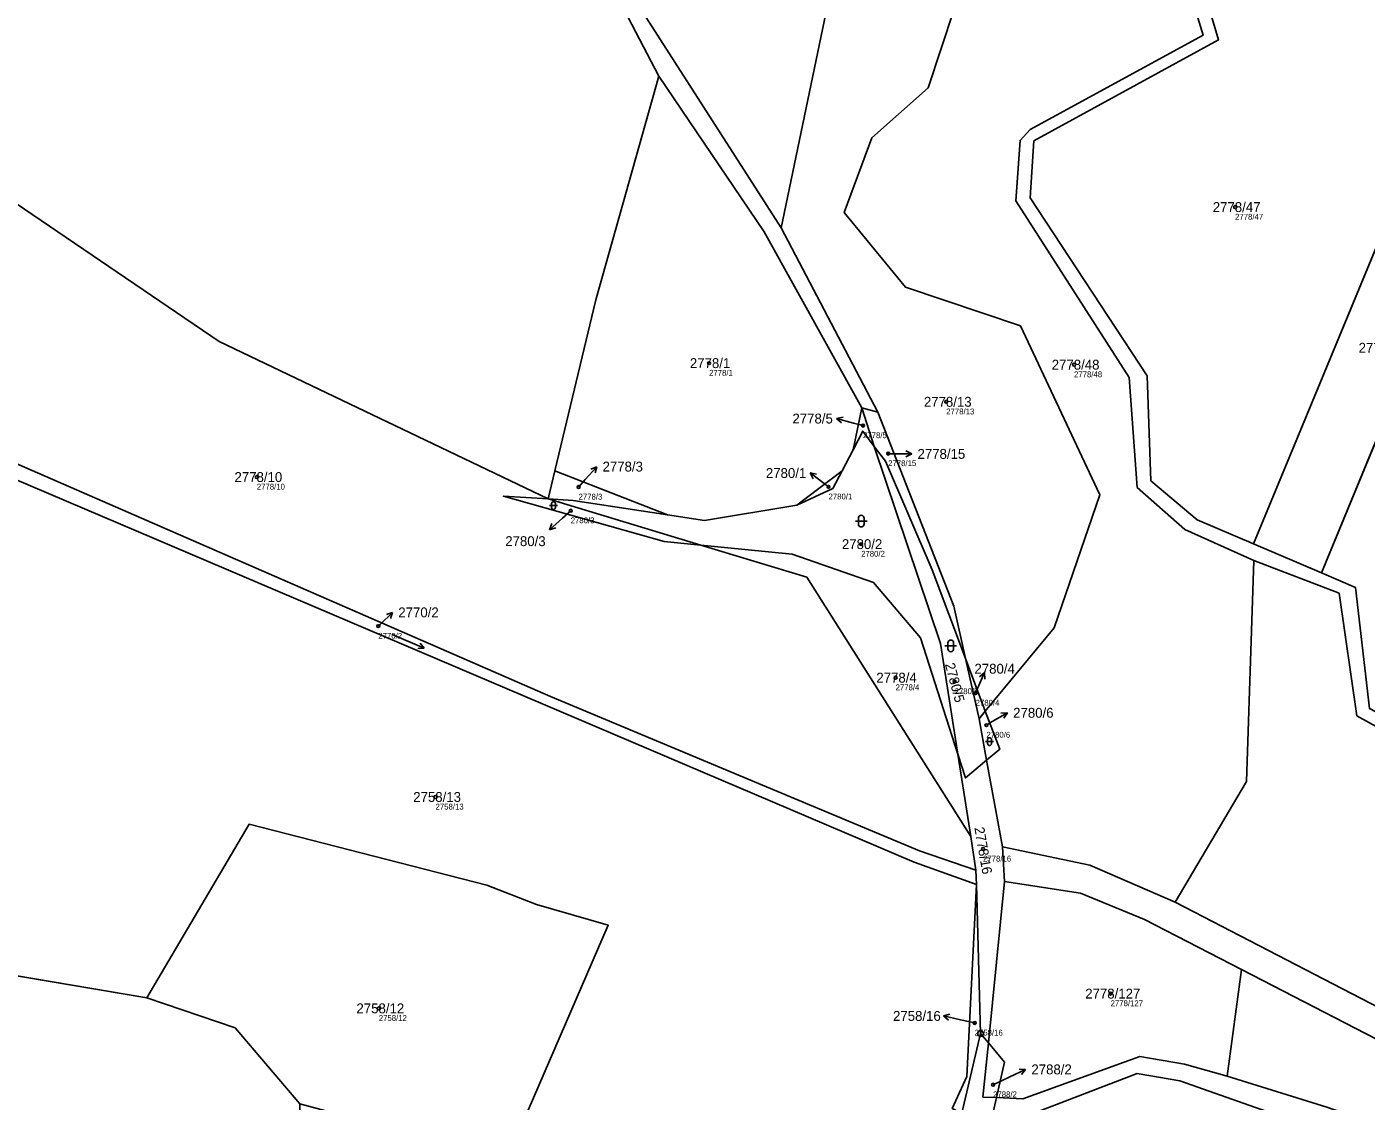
# Model space of a CAD drawing. Extents: x -739214 to -733252, y -1147612 to -1142842.
# Drawn here: x -738174 to -737943.5, y -1144060.6 to -1143875.8 of the extents above; entities that cross this region are included whole.
import ezdxf

# ---------------------------------------------------------------- set-up
doc = ezdxf.new("R2010")
doc.units = 0
for name, color, linetype in [('Definiční body', 7, 'Continuous'), ('Hranice parcel', 7, 'Continuous'), ('Parcelní čísla', 7, 'Continuous'), ('Polygon parcely', 7, 'Continuous'), ('Pop  PČ popisy', 7, 'Continuous'), ('Značky bodu BP', 7, 'Continuous'), ('Značky kultur', 7, 'Continuous')]:
    doc.layers.add(name, color=color, linetype=linetype)

msp = doc.modelspace()

# ---------------------------------------------------------------- linework, layer by layer
at = {"layer": 'Definiční body'}
for centre in [(-737966.1, -1143906.79), (-738056.61, -1143933.63), (-737993.81, -1143933.89), (-738015.81, -1143940.28), (-738030.12, -1143944.37), (-738025.8, -1143949.18), (-738134.44, -1143953.22), (-738079.07, -1143954.94), (-738036.06, -1143954.91), (-738080.42, -1143959.01), (-738030.45, -1143964.76), (-738113.53, -1143978.87), (-738024.52, -1143987.73), (-738014.36, -1143988.4), (-738010.74, -1143990.38), (-738008.89, -1143995.89), (-738103.68, -1144008.25), (-738009.47, -1144017.19), (-737987.52, -1144042.07), (-738113.45, -1144044.61), (-738010.91, -1144047.12), (-738007.74, -1144057.74)]:
    msp.add_circle(centre, 0.25, dxfattribs=at)
at = {"layer": 'Hranice parcel'}
for p, q in [((-738067.97, -1143873.37), (-738044.22, -1143910.38)), ((-737962.92, -1143964.73), (-737928.65, -1143881.88)), ((-737951.23, -1143969.71), (-737919.32, -1143892.38)), ((-738044.22, -1143910.38), (-738027.56, -1143942.04)), ((-738031.84, -1143948.55), (-738030.32, -1143941.32)), ((-738030.32, -1143941.32), (-738027.56, -1143942.04)), ((-738028.18, -1143947.96), (-738030.32, -1143941.32)), ((-738033.69, -1143952.13), (-738031.84, -1143948.55)), ((-738083.17, -1143952.17), (-738084.33, -1143956.99)), ((-738083.17, -1143952.17), (-738063.76, -1143959.71)), ((-738041.51, -1143958.03), (-738033.69, -1143952.13)), ((-738084.33, -1143956.99), (-738058.03, -1143964.92)), ((-737951.23, -1143969.71), (-737962.92, -1143964.73)), ((-738012.49, -1143984.43), (-738009.08, -1143993.47)), ((-738012.49, -1143984.43), (-738010.16, -1143994.78)), ((-738010.16, -1143994.78), (-738009.08, -1143993.47)), ((-738008.85, -1144001.92), (-738010.16, -1143994.78)), ((-738011.6, -1144015.06), (-738013.82, -1144000.89)), ((-738006.12, -1144016.81), (-738008.85, -1144001.92)), ((-738010.7, -1144020.82), (-738011.6, -1144015.06)), ((-738005.79, -1144022.76), (-738006.12, -1144016.81)), ((-738010.6, -1144023.28), (-738010.7, -1144020.82)), ((-738009.89, -1144048.95), (-738010.6, -1144023.28)), ((-738008.56, -1144050.53), (-738005.79, -1144022.76)), ((-738182.49, -1144037.88), (-738153.39, -1144042.78)), ((-737964.98, -1144037.92), (-737967.49, -1144056.26)), ((-738013.1, -1144062.62), (-738009.89, -1144048.95)), ((-738009.89, -1144048.95), (-738008.56, -1144050.53)), ((-738007.14, -1144059.96), (-738007.93, -1144063.48))]:
    msp.add_line(p, q, dxfattribs=at)
for points in [[(-738065.26, -1143884.27), (-738091.73, -1143833.66), (-738103.08, -1143819.81), (-738132.34, -1143806.02), (-738171.18, -1143796.23)], [(-738180.98, -1143797.5), (-738199.77, -1143862.82), (-738207.28, -1143860.51), (-738207.77, -1143875.03), (-738179.98, -1143892.1), (-738180.4, -1143903.13), (-738140.92, -1143929.92), (-738084.33, -1143956.99)], [(-738044.22, -1143910.38), (-738036.53, -1143873.49), (-738031.79, -1143856.2), (-738028.28, -1143846.12)], [(-738009.08, -1143993.47), (-737997.26, -1143979.13), (-737989.38, -1143956.26), (-738003.04, -1143927.22), (-738022.83, -1143920.54), (-738033.34, -1143907.71), (-738028.6, -1143894.86), (-738018.91, -1143886.27), (-738014.46, -1143872.73), (-738021.06, -1143860.02)], [(-737975.48, -1143864.47), (-737971.61, -1143877.23), (-738001.39, -1143893.44), (-738003.11, -1143895.33), (-738003.85, -1143905.7), (-737984.35, -1143936.12), (-737982.97, -1143955.01), (-737974.74, -1143962.25), (-737962.9, -1143967.6)], [(-737962.92, -1143964.73), (-737972.6, -1143960.6), (-737980.58, -1143953.86), (-737981.23, -1143935.79), (-738001.39, -1143905.17), (-738000.73, -1143895.41), (-737968.96, -1143878.05), (-737972.8, -1143864.99)], [(-738065.26, -1143884.27), (-738076.08, -1143922.72), (-738083.17, -1143952.17)], [(-738030.32, -1143941.32), (-738047.12, -1143911.02), (-738065.26, -1143884.27)], [(-738010.7, -1144020.82), (-738020.43, -1144017.52), (-738083.92, -1143990.96), (-738199.57, -1143940.6)], [(-738027.56, -1143942.04), (-738014.52, -1143975.43), (-738012.49, -1143984.43)], [(-738031.84, -1143948.55), (-738030.17, -1143945.33), (-738028.18, -1143947.96)], [(-738010.6, -1144023.28), (-738021.31, -1144019.46), (-738191.61, -1143947.01)], [(-738028.18, -1143947.96), (-738026.27, -1143950.47), (-738018.25, -1143969.18), (-738012.49, -1143984.43)], [(-738013.82, -1144000.89), (-738016.81, -1143981.86), (-738028.18, -1143947.96)], [(-738041.51, -1143958.03), (-738035.34, -1143955.18), (-738033.69, -1143952.13)], [(-738058.03, -1143964.92), (-738064.35, -1143964.29), (-738091.99, -1143956.53), (-738084.33, -1143956.99)], [(-738084.33, -1143956.99), (-738080, -1143957.25), (-738063.76, -1143959.71)], [(-738063.76, -1143959.71), (-738057.43, -1143960.67), (-738041.51, -1143958.03)], [(-738058.03, -1143964.92), (-738039.81, -1143970.42), (-738011.6, -1144015.06)], [(-738013.82, -1144000.89), (-738020.26, -1143980.86), (-738028.32, -1143971.34), (-738042.31, -1143966.5), (-738058.03, -1143964.92)], [(-737976.39, -1144026.32), (-737964.13, -1144005.59), (-737962.9, -1143967.6)], [(-737962.9, -1143967.6), (-737948.21, -1143973.22), (-737945.17, -1143994.28), (-737928.64, -1144003.4), (-737921.57, -1144015.08), (-737906.93, -1144027.09), (-737905.8, -1144050.09)], [(-737901.52, -1144050.01), (-737904.54, -1144026.44), (-737920.17, -1144013.19), (-737925.93, -1144002.09), (-737942.95, -1143993.04), (-737945.38, -1143972.2), (-737951.23, -1143969.71)], [(-738009.08, -1143993.47), (-738006.6, -1144000.03), (-738008.85, -1144001.92)], [(-738008.85, -1144001.92), (-738012.51, -1144004.98), (-738013.82, -1144000.89)], [(-738127.05, -1144061.01), (-738091.39, -1144070.6), (-738073.95, -1144030.31), (-738086.33, -1144026.73), (-738094.88, -1144023.42), (-738135.77, -1144012.95), (-738153.39, -1144042.78)], [(-737976.39, -1144026.32), (-737991.07, -1144019.99), (-738006.12, -1144016.81)], [(-738014.77, -1144061.81), (-738012.25, -1144056.3), (-738010.6, -1144023.28)], [(-738005.79, -1144022.76), (-737992.71, -1144024.79), (-737981.66, -1144029.32), (-737964.98, -1144037.92)], [(-737905.8, -1144050.09), (-737922.91, -1144050.83), (-737927.84, -1144050.42), (-737933.22, -1144048.7), (-737976.39, -1144026.32)], [(-737964.98, -1144037.92), (-737934.66, -1144053.55), (-737929.32, -1144055.23), (-737923.72, -1144055.39), (-737913.71, -1144055.05)], [(-738153.39, -1144042.78), (-738138.19, -1144047.98), (-738127.05, -1144061.01)], [(-738007.14, -1144059.96), (-738009.49, -1144059.87), (-738008.56, -1144050.53)], [(-738008.56, -1144050.53), (-738005.77, -1144053.85), (-738007.14, -1144059.96)], [(-737967.49, -1144056.26), (-737974.8, -1144054.22), (-737982.5, -1144052.91), (-738002.61, -1144060.14), (-738007.14, -1144059.96)], [(-737949.57, -1144066.24), (-737975.58, -1144057.09), (-737982.96, -1144055.8), (-738002.53, -1144063.31)], [(-737967.49, -1144056.26), (-737950.32, -1144061.58), (-737944.21, -1144063.75), (-737932.49, -1144068.97), (-737914.29, -1144076.59)]]:
    msp.add_lwpolyline(points, dxfattribs=at)
at = {"layer": 'Polygon parcely'}
for points in [[(-738027.56, -1143942.04), (-738044.22, -1143910.38), (-738067.97, -1143873.37), (-738088.86, -1143829.81), (-738098.34, -1143817.54), (-738116.99, -1143809.15), (-738138.07, -1143800.54), (-738170.01, -1143791.07), (-738171.18, -1143796.23), (-738132.34, -1143806.02), (-738103.08, -1143819.81), (-738091.73, -1143833.66), (-738065.26, -1143884.27), (-738047.12, -1143911.02), (-738030.32, -1143941.32)], [(-738084.33, -1143956.99), (-738083.17, -1143952.17), (-738076.08, -1143922.72), (-738065.26, -1143884.27), (-738091.73, -1143833.66), (-738103.08, -1143819.81), (-738132.34, -1143806.02), (-738171.18, -1143796.23), (-738180.98, -1143797.5), (-738199.77, -1143862.82), (-738207.28, -1143860.51), (-738207.77, -1143875.03), (-738179.98, -1143892.1), (-738180.4, -1143903.13), (-738140.92, -1143929.92)], [(-738064.35, -1143964.29), (-738091.99, -1143956.53), (-738084.33, -1143956.99), (-738140.92, -1143929.92), (-738180.4, -1143903.13), (-738179.98, -1143892.1), (-738207.77, -1143875.03), (-738207.28, -1143860.51), (-738199.77, -1143862.82), (-738180.98, -1143797.5), (-738203.54, -1143800.41), (-738205.97, -1143800.99), (-738204.63, -1143809.59), (-738209.8, -1143876.34), (-738210.79, -1143915.35), (-738206.01, -1143930.42), (-738199.57, -1143940.6), (-738083.92, -1143990.96), (-738020.43, -1144017.52), (-738010.7, -1144020.82), (-738011.6, -1144015.06), (-738039.81, -1143970.42), (-738058.03, -1143964.92)], [(-738044.22, -1143910.38), (-738036.53, -1143873.49), (-738031.79, -1143856.2), (-738028.28, -1143846.12), (-738021.78, -1143829.01), (-738040.62, -1143803.61), (-738046.58, -1143797.6), (-738060.34, -1143843.69), (-738067.97, -1143873.37)], [(-737928.65, -1143881.88), (-737925.61, -1143874.9), (-737940.58, -1143860.49), (-737959.01, -1143842.75), (-737967.05, -1143864.94), (-737972.8, -1143864.99), (-737968.96, -1143878.05), (-738000.73, -1143895.41), (-738001.39, -1143905.17), (-737981.23, -1143935.79), (-737980.58, -1143953.86), (-737972.6, -1143960.6), (-737962.92, -1143964.73)], [(-738014.52, -1143975.43), (-738012.49, -1143984.43), (-738009.08, -1143993.47), (-737997.26, -1143979.13), (-737989.38, -1143956.26), (-738003.04, -1143927.22), (-738022.83, -1143920.54), (-738033.34, -1143907.71), (-738028.6, -1143894.86), (-738018.91, -1143886.27), (-738014.46, -1143872.73), (-738021.06, -1143860.02), (-738028.28, -1143846.12), (-738031.79, -1143856.2), (-738036.53, -1143873.49), (-738044.22, -1143910.38), (-738027.56, -1143942.04)], [(-737951.23, -1143969.71), (-737919.32, -1143892.38), (-737917.87, -1143888.6), (-737928.65, -1143881.88), (-737962.92, -1143964.73)], [(-738047.12, -1143911.02), (-738065.26, -1143884.27), (-738076.08, -1143922.72), (-738083.17, -1143952.17), (-738063.76, -1143959.71), (-738057.43, -1143960.67), (-738041.51, -1143958.03), (-738033.69, -1143952.13), (-738031.84, -1143948.55), (-738030.32, -1143941.32)], [(-737891.94, -1143963.09), (-737898.47, -1143962.53), (-737912.03, -1143972.55), (-737912.83, -1143972.23), (-737919.62, -1143969.52), (-737925.37, -1143960.57), (-737925.17, -1143950.47), (-737927.45, -1143933.51), (-737913.69, -1143898.24), (-737919.32, -1143892.38), (-737951.23, -1143969.71), (-737945.38, -1143972.2), (-737942.95, -1143993.04), (-737925.93, -1144002.09), (-737920.17, -1144013.19), (-737904.54, -1144026.44), (-737901.52, -1144050.01), (-737900.78, -1144050.09), (-737890.1, -1144057.86), (-737884.25, -1144040.98), (-737884.57, -1144036.42), (-737900.26, -1144026.72), (-737905.19, -1144013.46), (-737905.53, -1143996.13)], [(-738207.29, -1143940.26), (-738191.61, -1143947.01), (-738021.31, -1144019.46), (-738010.6, -1144023.28), (-738010.7, -1144020.82), (-738020.43, -1144017.52), (-738083.92, -1143990.96), (-738199.57, -1143940.6), (-738207.03, -1143937.38), (-738212.62, -1143935.51), (-738212.35, -1143938.56)], [(-738028.18, -1143947.96), (-738030.32, -1143941.32), (-738031.84, -1143948.55), (-738030.17, -1143945.33)], [(-738018.25, -1143969.18), (-738012.49, -1143984.43), (-738014.52, -1143975.43), (-738027.56, -1143942.04), (-738030.32, -1143941.32), (-738028.18, -1143947.96), (-738026.27, -1143950.47)], [(-738016.81, -1143981.86), (-738028.18, -1143947.96), (-738030.17, -1143945.33), (-738031.84, -1143948.55), (-738033.69, -1143952.13), (-738035.34, -1143955.18), (-738041.51, -1143958.03), (-738057.43, -1143960.67), (-738063.76, -1143959.71), (-738080, -1143957.25), (-738084.33, -1143956.99), (-738058.03, -1143964.92), (-738042.31, -1143966.5), (-738028.32, -1143971.34), (-738020.26, -1143980.86), (-738013.82, -1144000.89)], [(-738008.85, -1144001.92), (-738010.16, -1143994.78), (-738012.49, -1143984.43), (-738018.25, -1143969.18), (-738026.27, -1143950.47), (-738028.18, -1143947.96), (-738016.81, -1143981.86), (-738013.82, -1144000.89), (-738012.51, -1144004.98)], [(-738080, -1143957.25), (-738063.76, -1143959.71), (-738083.17, -1143952.17), (-738084.33, -1143956.99)], [(-738033.69, -1143952.13), (-738041.51, -1143958.03), (-738035.34, -1143955.18)], [(-738084.33, -1143956.99), (-738091.99, -1143956.53), (-738064.35, -1143964.29), (-738058.03, -1143964.92)], [(-738020.26, -1143980.86), (-738028.32, -1143971.34), (-738042.31, -1143966.5), (-738058.03, -1143964.92), (-738039.81, -1143970.42), (-738011.6, -1144015.06), (-738013.82, -1144000.89)], [(-737976.39, -1144026.32), (-737933.22, -1144048.7), (-737927.84, -1144050.42), (-737922.91, -1144050.83), (-737905.8, -1144050.09), (-737906.93, -1144027.09), (-737921.57, -1144015.08), (-737928.64, -1144003.4), (-737945.17, -1143994.28), (-737948.21, -1143973.22), (-737962.9, -1143967.6), (-737964.13, -1144005.59)], [(-738010.16, -1143994.78), (-738009.08, -1143993.47), (-738012.49, -1143984.43)], [(-738008.85, -1144001.92), (-738006.6, -1144000.03), (-738009.08, -1143993.47), (-738010.16, -1143994.78)], [(-738005.79, -1144022.76), (-738006.12, -1144016.81), (-738008.85, -1144001.92), (-738012.51, -1144004.98), (-738013.82, -1144000.89), (-738011.6, -1144015.06), (-738010.7, -1144020.82), (-738010.6, -1144023.28), (-738009.89, -1144048.95), (-738008.56, -1144050.53)], [(-738138.19, -1144047.98), (-738127.05, -1144061.01), (-738091.39, -1144070.6), (-738073.95, -1144030.31), (-738086.33, -1144026.73), (-738094.88, -1144023.42), (-738135.77, -1144012.95), (-738153.39, -1144042.78)], [(-738009.89, -1144048.95), (-738010.6, -1144023.28), (-738012.25, -1144056.3), (-738014.77, -1144061.81), (-738013.1, -1144062.62)], [(-738005.77, -1144053.85), (-738007.14, -1144059.96), (-738002.61, -1144060.14), (-737982.5, -1144052.91), (-737974.8, -1144054.22), (-737967.49, -1144056.26), (-737964.98, -1144037.92), (-737981.66, -1144029.32), (-737992.71, -1144024.79), (-738005.79, -1144022.76), (-738008.56, -1144050.53)], [(-738173.58, -1144069.2), (-738136.12, -1144099.8), (-738125, -1144121.52), (-738109.86, -1144108.18), (-738121.83, -1144094.15), (-738126.02, -1144084.05), (-738127.31, -1144079.52), (-738127.05, -1144061.01), (-738138.19, -1144047.98), (-738153.39, -1144042.78), (-738182.49, -1144037.88), (-738184.48, -1144061.95)], [(-737950.32, -1144061.58), (-737944.21, -1144063.75), (-737932.49, -1144068.97), (-737914.29, -1144076.59), (-737913.71, -1144055.05), (-737923.72, -1144055.39), (-737929.32, -1144055.23), (-737934.66, -1144053.55), (-737964.98, -1144037.92), (-737967.49, -1144056.26)], [(-738007.14, -1144059.96), (-738009.49, -1144059.87), (-738008.56, -1144050.53), (-738009.89, -1144048.95), (-738013.1, -1144062.62), (-738011.1, -1144063.58), (-738007.93, -1144063.48)], [(-738007.14, -1144059.96), (-738005.77, -1144053.85), (-738008.56, -1144050.53), (-738009.49, -1144059.87)], [(-737982.96, -1144055.8), (-738002.53, -1144063.31), (-738014.98, -1144092.16), (-738001.58, -1144104.9), (-737993.61, -1144110.81), (-737983.92, -1144117.66), (-737975.97, -1144130.27), (-737962.5, -1144100.82), (-737952.27, -1144075.17), (-737949.57, -1144066.24), (-737975.58, -1144057.09)]]:
    msp.add_lwpolyline(points, close=True, dxfattribs=at)
for points in [[(-738014.46, -1143872.73), (-738018.91, -1143886.27), (-738028.6, -1143894.86), (-738033.34, -1143907.71), (-738022.83, -1143920.54), (-738003.04, -1143927.22), (-737989.38, -1143956.26), (-737997.26, -1143979.13), (-738009.08, -1143993.47), (-738006.6, -1144000.03), (-738008.85, -1144001.92), (-738006.12, -1144016.81), (-737991.07, -1144019.99), (-737976.39, -1144026.32), (-737964.13, -1144005.59), (-737962.9, -1143967.6), (-737974.74, -1143962.25), (-737982.97, -1143955.01), (-737984.35, -1143936.12), (-738003.85, -1143905.7), (-738003.11, -1143895.33), (-738001.39, -1143893.44), (-737971.61, -1143877.23), (-737975.48, -1143864.47)], [(-737975.48, -1143864.47), (-737971.61, -1143877.23), (-738001.39, -1143893.44), (-738003.11, -1143895.33), (-738003.85, -1143905.7), (-737984.35, -1143936.12), (-737982.97, -1143955.01), (-737974.74, -1143962.25), (-737962.9, -1143967.6), (-737948.21, -1143973.22), (-737945.17, -1143994.28), (-737928.64, -1144003.4)], [(-737942.95, -1143993.04), (-737945.38, -1143972.2), (-737951.23, -1143969.71), (-737962.92, -1143964.73), (-737972.6, -1143960.6), (-737980.58, -1143953.86), (-737981.23, -1143935.79), (-738001.39, -1143905.17), (-738000.73, -1143895.41), (-737968.96, -1143878.05), (-737972.8, -1143864.99)], [(-738014.77, -1144061.81), (-738012.25, -1144056.3), (-738010.6, -1144023.28), (-738021.31, -1144019.46), (-738191.61, -1143947.01)], [(-738182.49, -1144037.88), (-738153.39, -1144042.78), (-738135.77, -1144012.95), (-738094.88, -1144023.42), (-738086.33, -1144026.73), (-738073.95, -1144030.31), (-738091.39, -1144070.6)], [(-737933.22, -1144048.7), (-737976.39, -1144026.32), (-737991.07, -1144019.99), (-738006.12, -1144016.81), (-738005.79, -1144022.76), (-737992.71, -1144024.79), (-737981.66, -1144029.32), (-737964.98, -1144037.92), (-737934.66, -1144053.55)], [(-737932.49, -1144068.97), (-737944.21, -1144063.75), (-737950.32, -1144061.58), (-737967.49, -1144056.26), (-737974.8, -1144054.22), (-737982.5, -1144052.91), (-738002.61, -1144060.14), (-738007.14, -1144059.96), (-738007.93, -1144063.48), (-738002.53, -1144063.31), (-737982.96, -1144055.8), (-737975.58, -1144057.09), (-737949.57, -1144066.24), (-737919.88, -1144077.7)]]:
    msp.add_lwpolyline(points, dxfattribs=at)
at = {"layer": 'Pop  PČ popisy'}
for p, q in [((-738034.66, -1143943.15), (-738033.56, -1143942.93)), ((-738031.76, -1143943.93), (-738034.66, -1143943.15)), ((-738034.66, -1143943.15), (-738033.82, -1143943.9)), ((-738030.12, -1143944.37), (-738031.76, -1143943.93)), ((-738021.75, -1143949.24), (-738022.75, -1143948.74)), ((-738024.75, -1143949.24), (-738025.85, -1143949.24)), ((-738024.75, -1143949.24), (-738021.75, -1143949.24)), ((-738021.75, -1143949.24), (-738022.75, -1143949.74)), ((-738077.94, -1143953.67), (-738075.93, -1143951.44)), ((-738075.93, -1143951.44), (-738076.97, -1143951.85)), ((-738075.93, -1143951.44), (-738076.23, -1143952.52)), ((-738036.83, -1143954.33), (-738039.23, -1143952.52)), ((-738039.23, -1143952.52), (-738038.13, -1143952.73)), ((-738039.23, -1143952.52), (-738038.73, -1143953.53)), ((-738079.07, -1143954.94), (-738077.94, -1143953.67)), ((-738036.06, -1143954.91), (-738036.83, -1143954.33)), ((-738081.84, -1143960.27), (-738084.07, -1143962.28)), ((-738080.42, -1143959.01), (-738081.84, -1143960.27)), ((-738084.07, -1143962.28), (-738083.66, -1143961.24)), ((-738084.07, -1143962.28), (-738082.99, -1143961.98)), ((-738113.53, -1143978.87), (-738113.24, -1143978.59)), ((-738113.24, -1143978.59), (-738111.08, -1143976.51)), ((-738111.08, -1143976.51), (-738112.15, -1143976.84)), ((-738111.08, -1143976.51), (-738111.45, -1143977.56)), ((-738010.4, -1143989.6), (-738009.23, -1143986.84)), ((-738009.23, -1143986.84), (-738010.08, -1143987.56)), ((-738009.23, -1143986.84), (-738009.16, -1143987.96)), ((-738010.74, -1143990.38), (-738010.4, -1143989.6)), ((-738007.88, -1143995.29), (-738005.28, -1143993.79)), ((-738005.28, -1143993.79), (-738006.4, -1143993.86)), ((-738005.28, -1143993.79), (-738005.9, -1143994.72)), ((-738008.89, -1143995.89), (-738007.88, -1143995.29)), ((-738016.27, -1144045.9), (-738015.19, -1144045.63)), ((-738013.35, -1144046.57), (-738016.27, -1144045.9)), ((-738016.27, -1144045.9), (-738015.41, -1144046.61)), ((-738010.91, -1144047.12), (-738013.35, -1144046.57)), ((-738007.74, -1144057.74), (-738004.86, -1144056.39)), ((-738004.86, -1144056.39), (-738002.14, -1144055.12)), ((-738002.14, -1144055.12), (-738003.26, -1144055.09)), ((-738002.14, -1144055.12), (-738002.84, -1144056))]:
    msp.add_line(p, q, dxfattribs=at)
at = {"layer": 'Značky bodu BP'}
for radius in [0.5, 0.0303]:
    msp.add_circle((-738009.89, -1144048.95), radius, dxfattribs=at)
at = {"layer": 'Značky kultur'}
for p, q in [((-738083.72, -1143957.79), (-738083.72, -1143958.47)), ((-738083.06, -1143958.47), (-738083.06, -1143957.79)), ((-738084.06, -1143958.13), (-738082.72, -1143958.13)), ((-738031.43, -1143960.8), (-738029.43, -1143960.8)), ((-738030.93, -1143960.3), (-738030.93, -1143961.3)), ((-738029.93, -1143961.3), (-738029.93, -1143960.3)), ((-738111.16, -1143980.29), (-738105.64, -1143982.64)), ((-738105.64, -1143982.64), (-738106.73, -1143982.72)), ((-738105.64, -1143982.64), (-738106.34, -1143981.79)), ((-738016.03, -1143982.26), (-738014.03, -1143982.26)), ((-738015.53, -1143981.76), (-738015.53, -1143982.76)), ((-738014.53, -1143982.76), (-738014.53, -1143981.76)), ((-738009.02, -1143998.72), (-738007.68, -1143998.72)), ((-738008.69, -1143998.39), (-738008.69, -1143999.06)), ((-738008.02, -1143999.06), (-738008.02, -1143998.39))]:
    msp.add_line(p, q, dxfattribs=at)
for centre, radius, start, end in [((-738083.39, -1143957.8), 0.335, 0, 180), ((-738083.39, -1143958.47), 0.335, 180, 359.9879), ((-738030.43, -1143960.3), 0.5, 0, 180), ((-738030.43, -1143961.3), 0.5, 180, 359.9879), ((-738015.03, -1143981.76), 0.5, 0, 180), ((-738015.03, -1143982.76), 0.5, 180, 359.9879), ((-738008.35, -1143998.39), 0.335, 0, 180), ((-738008.35, -1143999.06), 0.335, 180, 359.9879)]:
    msp.add_arc(centre, radius, start, end, dxfattribs=at)

# ---------------------------------------------------------------- texts
at = {"layer": 'Definiční body'}
for s, p in [('2778/47', (-737966.1, -1143908.95)), ('2778/1', (-738056.61, -1143935.79)), ('2778/48', (-737993.81, -1143936.05)), ('2778/13', (-738015.81, -1143942.44)), ('2778/5', (-738030.12, -1143946.53)), ('2778/15', (-738025.8, -1143951.34)), ('2778/10', (-738134.44, -1143955.38)), ('2778/3', (-738079.07, -1143957.1)), ('2780/1', (-738036.06, -1143957.07)), ('2780/3', (-738080.42, -1143961.17)), ('2780/2', (-738030.45, -1143966.92)), ('2770/2', (-738113.53, -1143981.03)), ('2778/4', (-738024.52, -1143989.89)), ('2780/5', (-738014.36, -1143990.56)), ('2780/4', (-738010.74, -1143992.54)), ('2780/6', (-738008.89, -1143998.05)), ('2758/13', (-738103.68, -1144010.41)), ('2778/16', (-738009.47, -1144019.35)), ('2778/127', (-737987.52, -1144044.23)), ('2758/12', (-738113.45, -1144046.77)), ('2758/16', (-738010.91, -1144049.28)), ('2788/2', (-738007.74, -1144059.9))]:
    msp.add_text(s, height=1, dxfattribs=at).set_placement(p)
at = {"layer": 'Parcelní čísla'}
for s, p in [('2778/47', (-737969.94, -1143907.64)), ('2778/49', (-737944.84, -1143931.84)), ('2778/1', (-738059.92, -1143934.48)), ('2778/48', (-737997.65, -1143934.74)), ('2778/13', (-738019.65, -1143941.13)), ('2778/5', (-738042.27, -1143944.01)), ('2778/15', (-738020.75, -1143950.09)), ('2778/3', (-738074.95, -1143952.27)), ('2778/10', (-738138.28, -1143954.07)), ('2780/1', (-738046.84, -1143953.38)), ('2780/3', (-738091.69, -1143965.1)), ('2780/2', (-738033.76, -1143965.61)), ('2770/2', (-738110.09, -1143977.35)), ('2780/4', (-738010.95, -1143987.04)), ('2778/4', (-738027.83, -1143988.58)), ('2780/6', (-738004.29, -1143994.62)), ('2758/13', (-738107.52, -1144009.1)), ('2778/127', (-737991.89, -1144042.92)), ('2758/12', (-738117.29, -1144045.46)), ('2758/16', (-738024.96, -1144046.76)), ('2788/2', (-738001.15, -1144055.96))]:
    msp.add_text(s, height=1.7, dxfattribs=at).set_placement(p)
for s, rotation, p in [('2780/5', 285, (-738016.04, -1143985.43)), ('2778/16', 280, (-738010.97, -1144013.56))]:
    msp.add_text(s, height=1.7, rotation=rotation, dxfattribs=at).set_placement(p)

doc.saveas('drawing.dxf')
